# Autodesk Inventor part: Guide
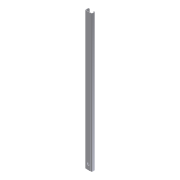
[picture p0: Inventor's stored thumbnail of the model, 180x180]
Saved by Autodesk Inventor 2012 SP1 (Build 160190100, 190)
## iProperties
Created: 2006-09
Part Number: Guide
Document SubType Name: Modeling
Mass: 16.263 g
Surface Area: 334.327 cm^2
Volume: 16.263 cm^3
Density: 1 g/cm^3
Material: Default
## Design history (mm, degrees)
sketch "Sketch1"
  geometry: L1 (-9.75, 2)-(-9.75, 8.5) reference; L2 (-8.75, 8.5)-(-8.75, 2) reference; L3 (-8.25, 1.5)-(-4, 1.5) reference; L4 (-5, 0.5)-(-8.25, 0.5) reference; L5 (-4, 1.5)-(-4, 1) reference; L6 (-5, 0)-(-5, 0.5) reference; L7 (-4, 1)-(4, 1) reference; L8 (5, 0)-(-5, 0) reference; L9 (-6.25, 9)-(-8.25, 9) reference; L10 (-6.25, 10)-(-6.25, 9) reference; L11 (-8.25, 10)-(-6.25, 10) reference; L12 (4, 1)-(4, 1.5) reference; L13 (5, 0.5)-(5, 0) reference; L14 (6.25, 9)-(6.25, 10) reference; L15 (4, 1.5)-(8.25, 1.5) reference; L16 (8.25, 0.5)-(5, 0.5) reference; L17 (8.75, 2)-(8.75, 8.5) reference; L18 (9.75, 8.5)-(9.75, 2) reference; L19 (8.25, 9)-(6.25, 9) reference; L20 (6.25, 10)-(8.25, 10) reference; A1 r 1.5 centre (-8.25, 2) between (-9.75, 2) and (-8.25, 0.5) reference; A2 r 0.5 centre (-8.25, 2) between (-8.75, 2) and (-8.25, 1.5) reference; A3 r 0.5 centre (-8.25, 8.5) between (-8.25, 9) and (-8.75, 8.5) reference; A4 r 1.5 centre (-8.25, 8.5) between (-8.25, 10) and (-9.75, 8.5) reference; A5 r 0.5 centre (8.25, 2) between (8.25, 1.5) and (8.75, 2) reference; A6 r 1.5 centre (8.25, 2) between (8.25, 0.5) and (9.75, 2) reference; A7 r 0.5 centre (8.25, 8.5) between (8.75, 8.5) and (8.25, 9) reference; A8 r 1.5 centre (8.25, 8.5) between (9.75, 8.5) and (8.25, 10) reference; 2 further points
  constraints: 40 end point, 16 point on circle, 10 horizontal, 10 vertical, 8 centre point, 46 other
extrude "Extrusion1" new body sketch "Sketch1" stored distance "d0" = 400; taper "d1" = 0 deg
sketch "Sketch3"
  geometry: L1 (10, 0)-(10, -400) reference; L2 (10, 0)-(0, 0) reference; L3 (0, -400)-(10, -400) reference; C1 r 4 at (5, -385); 2 further points
  constraints: 1 centre point, 1 midpoint, 1 vertical alignment
  dimensions: "d9" = 15 distance from line of C1.centre L3; "d11" = 8 diameter of C1
extrude "Extrusion3" cut sketch "Sketch3" stored distance "d7" = 10; taper "d8" = 0 deg
body "Solid1"
